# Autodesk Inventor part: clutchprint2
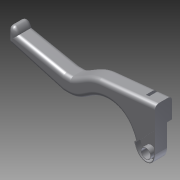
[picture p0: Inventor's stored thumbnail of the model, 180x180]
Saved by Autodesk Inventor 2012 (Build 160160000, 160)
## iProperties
Created: 2012-05
Part Number: clutchprint2
Material: Default
Document SubType Name: Modeling
Designer: Will
Density: 1 g/cm^3
Author: Will
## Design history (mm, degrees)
sketch "Sketch1"
  geometry: L1 (0, 0)-(0, -35.105); L2 (-75.129, -15.533)-(-113.381, -7.935); L3 (-75.129, -28.371)-(-118.348, -16.058); L4 (0, 0)-(-46.048, -4.791); L5 (0, -16.966)-(-16.929, -34.115); L6 (-8.752, -44.069)-(-5.999, -43.815); L7 (-120.193, -13.615)-(-120.193, -5.935); C1 r 3.746 at (-7.375, -37.782); A1 r 14.21 centre (-8.682, -29.792) between (-8.477, -44.001) and (-6.281, -43.798); A2 r 7.584 centre (-120.689, -9.963) between (-113.381, -7.935) and (-116.124, -3.907); A3 r 2.54 centre (-117.653, -5.935) between (-116.124, -3.907) and (-120.193, -5.935); A4 r 2.54 centre (-117.653, -13.615) between (-120.193, -13.615) and (-118.348, -16.058); 14 further points
  constraints: 14 end point, 8 point on circle, 5 centre point, 5 point on line, 4 tangent, 2 midpoint, 1 equal radius, 1 parallel, 1 vertical, 22 other
  dimensions: "d1" = 7.493 diameter of C1; "d2" = 37.78244 vertical distance of L1.start C1.centre; "d37" = 2.54 radius of A3
extrude "Extrusion1" new body sketch "Sketch1" stored distance "d3" = 14.097; taper "d4" = 0 deg
sketch "Sketch2"
  geometry: L1 (0, 0)-(0, -35.105); L2 (0, -16.966)-(-16.929, -34.115); L3 (-8.752, -44.069)-(-5.999, -43.815); C1 r 3.746 at (-7.375, -37.782); A1 r 14.21 centre (-8.682, -29.792) between (-8.477, -44.001) and (-6.281, -43.798); 11 further points
  constraints: 6 end point, 2 centre point, 2 midpoint, 2 point on line, 1 point on circle, 1 vertical, 16 other
  dimensions: "d5" = 7.493 diameter of C1; "d6" = 37.78244 vertical distance of L1.start C1.centre
extrude "Extrusion2" join sketch "Sketch2" stored distance "d7" = 5.842; taper "d8" = 0 deg
sketch "Sketch3"
  geometry: L1 (0, 16.966)-(14.097, 16.966) reference; L2 (8.954, 16.966)-(5.144, 16.966); L3 (5.144, 16.966)-(5.144, 5.967); L4 (5.144, 5.967)-(8.954, 5.967); L5 (8.954, 5.967)-(8.954, 16.966); 1 further point
  constraints: 8 end point, 2 parallel, 1 horizontal, 1 perpendicular, 1 point on line
  dimensions: "d9" = 10.9982 distance of L4.end L2.start; "d10" = 3.81 distance of L3.end L4.end; "d11" = 1.905 distance from line of point (7.049, 16.966) L5
extrude "Extrusion3" cut sketch "Sketch3" distance "d12" = 13.208; taper "d13" = 0 deg
sketch "Sketch4"
  geometry: L1 (0, 0)-(46.048, -4.791) reference; L2 (0, -16.966)-(0, 0) reference; C1 r 4.318 at (10.922, -9.691)
  constraints: 1 centre point
  dimensions: "d14" = 8.636 diameter of C1; "d15" = 10.922 distance from line of L2 C1.centre; "d16" = 8.509 distance from line of L1 C1.centre
extrude "Extrusion4" cut sketch "Sketch4" distance "d17" = 11.303; taper "d18" = 0 deg
sketch "Sketch5"
  geometry: L1 (0, -10.998)-(-6.807, -10.998) reference; L2 (0, 0)-(0, -16.966) reference; L3 (-6.807, -10.998)-(0, -10.998); L4 (0, -16.966)-(-6.807, -10.998); L5 (0, -10.998)-(0, -16.966)
  constraints: 6 end point, 2 collinear
extrude "Extrusion5" cut sketch "Sketch5" stored distance "d19" = 3.81; taper "d20" = 0 deg
fillet "Fillet1" dims "d21" = 3.429
sketch "Sketch6"
  geometry: L1 (0, 4.654)-(0, 0) reference; L2 (-13.208, 6.028)-(0, 4.654) reference; L3 (-13.208, -10.937)-(-13.208, 6.028) reference; L4 (-13.208, -10.937)-(-6.401, -4.97) reference; L5 (0, 4.654)-(-13.208, 6.028); L6 (-13.208, 6.028)-(-13.208, -10.937); L7 (-13.208, -10.937)-(-6.401, -4.97); L8 (0, 4.654)-(0, 0); L9 (-0.762, 3.967)-(-12.446, 5.183); L10 (-12.446, 5.183)-(-12.446, -9.256); L11 (-12.446, -9.256)-(-7.112, -4.58); L12 (-0.762, 3.967)-(-0.762, 0.909); A1 r 4.318 centre (-2.286, -3.663) between (0, 0) and (-6.401, -4.97) reference; A2 r 4.318 centre (-2.286, -3.663) between (0, 0) and (-6.401, -4.97); A3 r 4.806 centre (-2.406, -3.607) between (-0.762, 0.909) and (-7.112, -4.58)
  constraints: 16 end point, 5 parallel, 4 point on circle, 3 collinear, 2 centre point, 1 concentric
  dimensions: "d22" = 0.762 distance between parallel lines of L2 L9; "d23" = 0.762 distance between parallel lines of L4 L11; "d24" = 0.762 distance between parallel lines of L3 L10; "d25" = 0.762 distance between parallel lines of L1 L12; "d26" = 4.826 horizontal distance of A1.centre L11.end; "d27" = 4.572 vertical distance of L12.end A1.centre
extrude "Extrusion6" join sketch "Sketch6" stored distance "d28" = 25.4; taper "d29" = 0 deg
sketch "Sketch7"
  geometry: L1 (0, -16.966)-(0, -35.105) reference; L2 (-16.929, -34.115)-(0, -16.966) reference; L3 (-0.762, -18.822)-(-0.762, -35.003); L4 (-0.762, -18.822)-(-16.009, -34.267); 6 further points
  constraints: 4 end point, 2 parallel, 8 other
  dimensions: "d30" = 0.762 distance between parallel lines of L2 L4; "d31" = 0.762 distance between parallel lines of L1 L3
extrude "Extrusion7" join sketch "Sketch7" stored distance "d32" = 25.4; taper "d33" = 0 deg
sketch "Sketch8"
  geometry: C1 r 3.746 at (-7.375, -37.782) reference; C2 r 3.746 at (-7.375, -37.782); C3 r 4.128 at (-7.375, -37.782); 1 further point
  constraints: 2 centre point, 2 coincident, 1 concentric
  dimensions: "d34" = 8.255 diameter of C3
extrude "Extrusion8" join sketch "Sketch8" stored distance "d35" = 25.4; taper "d36" = 0 deg
sketch "Sketch9"
  geometry: L1 (12.446, -2.061)-(12.446, -5.119) reference; L2 (12.446, -5.651)-(12.446, 0.269); L3 (12.446, 0.269)-(9.41, 0.269); L4 (9.41, 0.269)-(10.922, -5.373); A1 r 4.318 centre (10.922, -9.691) between (12.446, -5.651) and (10.922, -5.373) reference; A2 r 4.318 centre (10.922, -9.691) between (12.446, -5.651) and (10.922, -5.373); 1 further point
  constraints: 6 end point, 4 point on circle, 2 point on line, 1 centre point, 1 concentric, 1 perpendicular
  dimensions: "d38" = 15 deg angle of L4 L2
extrude "Extrusion9" cut sketch "Sketch9" distance "d39" = 8.9662; taper "d40" = 0 deg
body "Solid1"
